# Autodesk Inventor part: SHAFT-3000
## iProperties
Company: Autodesk Inc.
Created: 2007-10
Part Number: SHAFT-3000
Document SubType Name: Modeling
Material: Steel
Density: 7.85 g/cm^3
Title: IFI Curriculum
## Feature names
1. Base1
